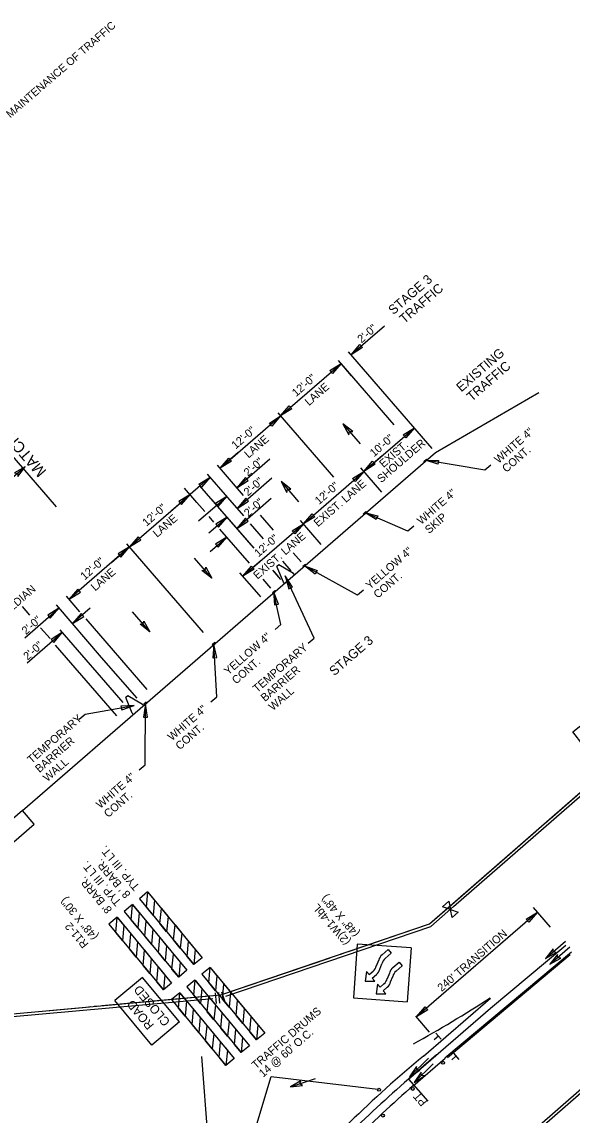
# Model space of a CAD drawing. Extents: x 259983 to 267998, y 211467 to 219827.
# Drawn here: x 265064 to 265890, y 214746 to 216385 of the extents above; entities that cross this region are included whole.
import ezdxf

# ---------------------------------------------------------------- set-up
doc = ezdxf.new("R2010")
doc.units = 0
for name, color, linetype in [('1', 7, 'Continuous'), ('Default', 7, 'Continuous'), ('Level 1', 7, 'Continuous'), ('Level 24', 7, 'Continuous'), ('Level 43', 7, 'Continuous'), ('Level 58', 7, 'Continuous'), ('R-W - CofA', 7, 'Continuous'), ('R_MOT', 7, 'Continuous'), ('R_MOT STAGE 1', 7, 'Continuous'), ('R_MOT STAGE 2', 7, 'Continuous'), ('ROAD', 7, 'Continuous'), ('STATIONING1', 7, 'Continuous')]:
    doc.layers.add(name, color=color, linetype=linetype)

msp = doc.modelspace()

# ---------------------------------------------------------------- linework, layer by layer
at = {"layer": '1'}
for p, q in [((265608.3, 215928.7), (265558.6, 215885.7)), ((265680, 215745.4), (265554.6, 215890.2)), ((265452.7, 215794), (265543.4, 215872.6)), ((265559.2, 215854.3), (265539.5, 215877.1)), ((265623.1, 215780.6), (265543.4, 215872.6)), ((265532.3, 215702.1), (265448.8, 215798.6)), ((265362, 215715.5), (265452.7, 215794)), ((265577.7, 215710.8), (265653.3, 215776.3)), ((265389.2, 215739.1), (265362, 215715.5)), ((265604.9, 215734.4), (265577.7, 215710.8)), ((265397.2, 215674.8), (265358.1, 215720)), ((265436.7, 215729.3), (265387.2, 215686.4)), ((265604.4, 215679.9), (265573.2, 215716)), ((265759.2, 215712.6), (265669.8, 215727.7)), ((265768, 215720.2), (265759.2, 215712.6)), ((265346.9, 215702.4), (265302.2, 215663.8)), ((265373.5, 215671.7), (265342.9, 215706.9)), ((265439.6, 215700.6), (265387.5, 215655.5)), ((265486.9, 215632.3), (265577.7, 215710.8)), ((265327.1, 215664.1), (265308.4, 215685.7)), ((265411.9, 215596.8), (265331.7, 215689.3)), ((265226, 215597.7), (265316.7, 215676.3)), ((265289.5, 215652.7), (265316.7, 215676.3)), ((265329.7, 215636.7), (265372, 215673.3)), ((265353.9, 215663.7), (265349.6, 215668.7)), ((265397.3, 215644.1), (265373.5, 215671.7)), ((265438.7, 215670.1), (265387.1, 215625.4)), ((265338.8, 215650.6), (265327.1, 215664.1)), ((265382.8, 215630.3), (265361, 215655.5)), ((265345.2, 215618.8), (265372.4, 215642.4)), ((265352.4, 215634.9), (265345.3, 215643.1)), ((265442.1, 215623), (265422.7, 215645.4)), ((265513.7, 215601.4), (265482.5, 215637.4)), ((265643.6, 215621.1), (265579.1, 215649.1)), ((265405.8, 215573.2), (265361.7, 215624.2)), ((265412.9, 215595.6), (265382.8, 215630.3)), ((265396.2, 215553.7), (265486.9, 215632.3)), ((265427, 215609.9), (265407.6, 215632.3)), ((265652.4, 215628.8), (265643.6, 215621.1)), ((265336.9, 215469.6), (265222, 215602.3)), ((265347.1, 215590.8), (265372, 215612.3)), ((265226, 215597.8), (265135.3, 215519.2)), ((265198.8, 215574.2), (265226, 215597.8)), ((265483.4, 215575.2), (265471.7, 215588.8)), ((265423.4, 215577.3), (265396.2, 215553.7)), ((265468.3, 215562.1), (265456.2, 215576.1)), ((265567.9, 215525.3), (265488.7, 215569.2)), ((265420.3, 215526), (265391.7, 215558.9)), ((265453.2, 215549), (265441.1, 215563)), ((265448.9, 215554), (265442.9, 215561)), ((265503, 215461), (265459.7, 215554.3)), ((265438.1, 215536), (265426.3, 215549.6)), ((265151.6, 215500.3), (265131.3, 215523.7)), ((265422.9, 215522.9), (265420.3, 215526)), ((265453.2, 215481.6), (265442.2, 215530.7)), ((265576.8, 215533), (265567.9, 215525.3)), ((265076.2, 215495.5), (265065.2, 215508.2)), ((265068.7, 215461.6), (265120.1, 215506.1)), ((265184.1, 215432.2), (265116.2, 215510.7)), ((265167, 215506), (265140.3, 215482.8)), ((265252.4, 215383.9), (265160.8, 215489.7)), ((265072.5, 215424.1), (265125.2, 215469.7)), ((265106.7, 215460.3), (265092.6, 215476.6)), ((265216.4, 215364.4), (265122, 215473.4)), ((265444.4, 215473.9), (265453.2, 215481.6)), ((265494.1, 215453.3), (265503, 215461)), ((265206.9, 215344.5), (265115.1, 215450.6)), ((265357, 215373.1), (265352.7, 215451.4)), ((265237.3, 215370.8), (265184.1, 215432.2)), ((265348.2, 215365.4), (265357, 215373.1)), ((265159.2, 215347.2), (265233.1, 215360)), ((265249.3, 215271.1), (265249.9, 215362.4)), ((265150.4, 215339.5), (265159.2, 215347.2)), ((265240.4, 215263.4), (265249.3, 215271.1))]:
    msp.add_line(p, q, dxfattribs=at)
for points in [[(265575.5, 215896.4), (265558.6, 215885.7), (265571.6, 215900.9)], [(265526.5, 215861.9), (265543.4, 215872.6), (265530.4, 215857.4)], [(265469.6, 215804.7), (265452.7, 215794), (265465.7, 215809.3)], [(265435.8, 215783.3), (265452.7, 215794), (265439.7, 215778.8)], [(265636.3, 215765.6), (265653.3, 215776.3), (265640.3, 215761)], [(265378.9, 215726.2), (265362, 215715.5), (265375, 215730.7)], [(265594.6, 215721.5), (265577.7, 215710.8), (265590.7, 215726)], [(265688.8, 215721.5), (265669.8, 215727.7), (265689.8, 215727.4)], [(265329.9, 215691.7), (265346.9, 215702.4), (265333.9, 215687.2)], [(265400.2, 215701.6), (265387.2, 215686.4), (265404.1, 215697.1)], [(265560.7, 215700.1), (265577.7, 215710.8), (265564.7, 215695.6)], [(265303.7, 215661.1), (265316.7, 215676.3), (265299.8, 215665.6)], [(265303.7, 215661.1), (265316.7, 215676.3), (265299.8, 215665.6)], [(265359, 215658.1), (265372, 215673.3), (265355.1, 215662.6)], [(265400.5, 215670.7), (265387.5, 215655.5), (265404.4, 215666.2)], [(265359.4, 215627.2), (265372.4, 215642.4), (265355.4, 215631.7)], [(265400.1, 215640.6), (265387.1, 215625.4), (265404, 215636.1)], [(265503.9, 215643), (265486.9, 215632.3), (265499.9, 215647.5)], [(265596.2, 215638.7), (265579.1, 215649.1), (265598.5, 215644.2)], [(265470, 215621.6), (265486.9, 215632.3), (265473.9, 215617.1)], [(265239, 215613), (265226, 215597.8), (265242.9, 215608.4)], [(265359, 215597.1), (265372, 215612.3), (265355, 215601.6)], [(265213, 215582.5), (265226, 215597.8), (265209, 215587.1)], [(265413.1, 215564.4), (265396.2, 215553.7), (265409.2, 215569)], [(265504.5, 215557), (265488.7, 215569.2), (265507.4, 215562.2)], [(265470.7, 215537.5), (265459.7, 215554.3), (265465.2, 215535)], [(265148.3, 215534.4), (265135.3, 215519.2), (265152.2, 215529.9)], [(265449.3, 215511.9), (265442.2, 215530.7), (265443.5, 215510.7)], [(265107.1, 215490.9), (265120.1, 215506.1), (265103.2, 215495.4)], [(265153.3, 215498), (265140.3, 215482.8), (265157.2, 215493.5)], [(265112.2, 215454.5), (265125.2, 215469.7), (265108.2, 215459)], [(265356.8, 215431.8), (265352.7, 215451.4), (265350.8, 215431.5)], [(265214.2, 215353.3), (265233.1, 215360), (265213.1, 215359.2)], [(265252.7, 215342.6), (265249.9, 215362.4), (265246.7, 215342.6)], [(265821, 215039.6), (265838, 215050.3), (265824.9, 215035.1)], [(265673.4, 214903.9), (265656.5, 214893.2), (265669.5, 214908.4)]]:
    msp.add_lwpolyline(points, close=True, dxfattribs=at)
at = {"layer": 'Default'}
for p, q in [((265685.2, 215739.3), (265840.1, 215829.1)), ((265065.3, 215202.6), (265685.2, 215739.3)), ((265449.9, 215570.9), (265447.2, 215568.5)), ((265456.8, 215544.9), (265447.2, 215568.5)), ((265471.9, 215558), (265449.9, 215570.9)), ((265473.6, 215556.1), (265471.9, 215558)), ((265458.4, 215543), (265456.8, 215544.9)), ((265223.2, 215374.6), (265220.4, 215372.2)), ((265230.1, 215348.6), (265220.4, 215372.2)), ((265245.2, 215361.7), (265223.2, 215374.6)), ((265246.8, 215359.8), (265245.2, 215361.7)), ((265231.7, 215346.7), (265230.1, 215348.6))]:
    msp.add_line(p, q, dxfattribs=at)
for points in [[(265667.6, 215725.8), (265671.4, 215729.1), (265672.3, 215728.1), (265668.4, 215724.8)], [(265576.9, 215647.2), (265580.7, 215650.6), (265581.6, 215649.6), (265577.7, 215646.3)], [(265486, 215568.6), (265489.9, 215571.9), (265490.7, 215570.9), (265486.9, 215567.6)], [(265444.2, 215532.3), (265440.3, 215529), (265441.2, 215528), (265445, 215531.4)], [(265353.9, 215454.2), (265350, 215450.8), (265350.9, 215449.8), (265354.7, 215453.2)], [(265251.1, 215365.2), (265247.2, 215361.9), (265248.1, 215360.9), (265251.9, 215364.2)]]:
    msp.add_lwpolyline(points, close=True, dxfattribs=at)
at = {"layer": 'Level 43'}
for points in [[(265546.2, 215782), (265572.2, 215752)], [(265069.6, 215717.7), (265039.6, 215691.7)], [(265453.3, 215695.6), (265479.3, 215665.5)], [(265349.3, 215551), (265323.3, 215581)], [(265256.5, 215470.6), (265230.5, 215500.6)], [(265850.2, 214980.9), (265880.3, 215006.9)], [(265856.8, 214972.2), (265886.8, 214998.2)], [(265646.1, 214803.5), (265674.5, 214831.3)], [(265653.2, 214795.2), (265681.6, 214823)], [(265467.3, 214788.4), (265504.9, 214801.1)]]:
    msp.add_lwpolyline(points, dxfattribs=at)
at = {"layer": 'Level 58'}
for points in [[(265560.8, 215770.8), (265546.2, 215782), (265555.2, 215765.9), (265556, 215770.6)], [(265058.4, 215703.1), (265069.6, 215717.7), (265053.5, 215708.7), (265058.2, 215707.9)], [(265467.9, 215684.4), (265453.3, 215695.6), (265462.2, 215679.5), (265463.1, 215684.2)], [(265340.4, 215567.1), (265349.3, 215551), (265334.7, 215562.2), (265339.5, 215562.4)], [(265247.5, 215486.6), (265256.5, 215470.6), (265241.8, 215481.7), (265246.6, 215481.9)], [(265861.4, 214995.5), (265850.2, 214980.9), (265866.3, 214989.8), (265861.6, 214990.7)], [(265868, 214986.8), (265856.8, 214972.2), (265872.9, 214981.1), (265868.2, 214982)], [(265656.4, 214818.8), (265646.1, 214803.5), (265661.6, 214813.4), (265656.8, 214814)], [(265483.2, 214797.7), (265467.3, 214788.4), (265485.6, 214790.6), (265481.5, 214793.2)], [(265663.4, 214810.5), (265653.2, 214795.2), (265668.7, 214805.1), (265663.9, 214805.7)]]:
    msp.add_lwpolyline(points, close=True, dxfattribs=at)
at = {"layer": 'R-W - CofA'}
for p, q in [((265695.8, 215058.5), (265705.2, 215066.7)), ((265705.2, 215066.7), (265707.6, 215054.5)), ((265707.6, 215054.5), (265695.8, 215058.5)), ((265710, 215042.3), (265707.6, 215054.5)), ((265707.6, 215054.5), (265719.3, 215050.5)), ((265719.3, 215050.5), (265710, 215042.3)), ((265354.4, 214929.3), (265355.9, 214913.6)), ((265359.7, 214929.8), (265361.1, 214914)), ((265364, 214930.7), (265369.1, 214915.7)), ((265050.7, 214898.1), (265362.9, 214926.4))]:
    msp.add_line(p, q, dxfattribs=at)
for points in [[(265362.9, 214926.4), (265676, 215032.6), (265937.7, 215260.6), (265891.1, 215320.8), (266161.5, 215534.1)], [(265712.3, 215058.6), (265943.4, 215260), (265916.6, 215294.8)], [(265857, 215190.3), (265937.7, 215260.6), (265913.1, 215292.3)], [(265622.7, 214398.8), (265711.4, 214612.4), (266239.1, 215072.3), (266415.9, 215240.2)], [(265839.2, 215174.8), (265844, 215179)], [(265848.1, 215182.5), (265852.9, 215186.7)], [(265709.5, 215061.8), (265835.1, 215171.2)], [(265554.4, 214991.3), (265676, 215032.6), (265709.5, 215061.8)], [(265370.5, 214924.5), (265678.1, 215028.8), (265712.3, 215058.6)], [(265369.2, 214928.5), (265527, 214982)], [(265532, 214983.8), (265538.1, 214985.8)], [(265543.2, 214987.5), (265549.3, 214989.6)], [(265837.2, 214727.6), (266105.3, 214961.2)], [(265045.3, 214893.4), (265351, 214921.1)], [(265184.6, 214910.2), (265350.6, 214925.3)], [(265050.7, 214898.1), (265155.8, 214907.6)], [(265161.1, 214908.1), (265167.5, 214908.7)], [(265172.9, 214909.2), (265179.3, 214909.8)], [(265840, 214724.5), (265963.3, 214831.9)]]:
    msp.add_lwpolyline(points, dxfattribs=at)
at = {"layer": 'R_MOT'}
for p, q in [((265253.1, 215080.6), (265240.7, 215070.3)), ((265253.1, 215080.6), (265334.9, 214982)), ((265230.2, 215061.6), (265217.9, 215051.4)), ((265230.2, 215061.6), (265312, 214963.1)), ((265240.7, 215070.3), (265322.5, 214971.8)), ((265217.9, 215051.4), (265299.7, 214952.8)), ((265207.3, 215042.6), (265194.9, 215032.3)), ((265194.9, 215032.3), (265276.7, 214933.8)), ((265207.3, 215042.6), (265289.1, 214944.1)), ((265567.7, 215002.4), (265561.9, 214921.7)), ((265648.5, 214996.7), (265567.7, 215002.4)), ((265604.8, 214986.3), (265613.9, 214994.2)), ((265613.9, 214994.2), (265618.6, 214988.8)), ((265648.5, 214996.7), (265642.7, 214915.9)), ((265334.9, 214982), (265322.5, 214971.8)), ((265596.5, 214969.6), (265599.9, 214978.3)), ((265609.5, 214980.9), (265618.6, 214988.8)), ((265312, 214963.1), (265299.7, 214952.8)), ((265312, 214963.1), (265299.7, 214952.8)), ((265347, 214967.4), (265334.7, 214957.2)), ((265347, 214967.4), (265428.8, 214868.9)), ((265581.7, 214961.3), (265579.5, 214946.9)), ((265581.7, 214961.3), (265585.6, 214956.8)), ((265585.6, 214956.8), (265591.3, 214961.8)), ((265601.3, 214964.7), (265604.6, 214972.9)), ((265621.2, 214967.4), (265630.3, 214975.3)), ((265625.8, 214962), (265634.9, 214969.9)), ((265630.3, 214975.3), (265634.9, 214969.9)), ((265245.5, 214952.5), (265203.7, 214917.8)), ((265301, 214885.7), (265245.5, 214952.5)), ((265324.1, 214948.4), (265311.8, 214938.2)), ((265324.1, 214948.4), (265405.9, 214849.9)), ((265334.7, 214957.2), (265416.5, 214858.7)), ((265579.5, 214946.9), (265594.1, 214947)), ((265590.2, 214951.5), (265596.4, 214956.8)), ((265590.2, 214951.5), (265594.1, 214947)), ((265612.8, 214950.8), (265616.3, 214959.4)), ((265617.7, 214945.9), (265620.9, 214954)), ((265289.1, 214944.1), (265276.7, 214933.8)), ((265301.2, 214929.4), (265288.9, 214919.2)), ((265289, 214944.1), (265289, 214944)), ((265301.2, 214929.4), (265383.1, 214830.9)), ((265311.8, 214938.2), (265393.6, 214839.7)), ((265598, 214942.5), (265595.8, 214928)), ((265598, 214942.5), (265601.9, 214938)), ((265601.9, 214938), (265607.6, 214943)), ((265606.6, 214932.6), (265612.7, 214937.9)), ((265606.6, 214932.6), (265610.4, 214928.1)), ((265259.2, 214851), (265203.7, 214917.8)), ((265288.9, 214919.2), (265370.7, 214820.6)), ((265561.9, 214921.7), (265642.7, 214915.8)), ((265595.8, 214928), (265610.4, 214928.1)), ((265301, 214885.7), (265259.2, 214851)), ((265428.8, 214868.9), (265416.5, 214858.7)), ((265689.7, 214864.5), (265683.3, 214858.9)), ((265685.7, 214869.1), (265693.7, 214859.9)), ((265405.9, 214849.9), (265393.6, 214839.7)), ((265405.9, 214849.9), (265393.6, 214839.7)), ((265383.1, 214830.9), (265370.7, 214820.6)), ((265383, 214831), (265382.9, 214830.8)), ((265715.8, 214834.3), (265709.4, 214828.8)), ((265711.9, 214838.9), (265719.9, 214829.7))]:
    msp.add_line(p, q, dxfattribs=at)
for points in [[(265261.2, 215045.7), (265251.2, 215057.8), (265253.3, 215080.3), (265263.3, 215068.2)], [(265238.3, 215026.7), (265228.3, 215038.8), (265230.4, 215061.3), (265240.4, 215049.3)], [(265281.6, 215021), (265271.6, 215033.2), (265273.7, 215055.7), (265283.7, 215043.6)], [(265215.4, 215007.6), (265205.4, 215019.8), (265207.5, 215042.3), (265217.5, 215030.2)], [(265258.8, 215002.1), (265248.8, 215014.2), (265250.9, 215036.7), (265260.9, 215024.6)], [(265302.1, 214996.4), (265292.1, 215008.6), (265294.2, 215031.1), (265304.2, 215019)], [(265235.9, 214983), (265225.8, 214995.2), (265227.9, 215017.7), (265237.9, 215005.6)], [(265279.2, 214977.4), (265269.2, 214989.6), (265271.3, 215012.1), (265281.3, 215000)], [(265322.5, 214971.8), (265312.5, 214983.9), (265314.6, 215006.5), (265324.6, 214994.4)], [(265256.3, 214958.4), (265246.3, 214970.5), (265248.4, 214993.1), (265258.4, 214981)], [(265299.7, 214952.8), (265289.6, 214965), (265291.7, 214987.5), (265301.8, 214975.4)], [(265276.7, 214933.8), (265266.7, 214945.9), (265268.8, 214968.4), (265278.8, 214956.4)], [(265355.1, 214932.5), (265345.1, 214944.7), (265347.2, 214967.2), (265357.2, 214955.1)], [(265332.3, 214913.5), (265322.3, 214925.7), (265324.4, 214948.2), (265334.4, 214936.1)], [(265309.4, 214894.5), (265299.3, 214906.6), (265301.4, 214929.1), (265311.4, 214917.1)], [(265375.6, 214907.9), (265365.6, 214920), (265367.7, 214942.6), (265377.7, 214930.5)], [(265352.7, 214888.9), (265342.7, 214901.1), (265344.8, 214923.6), (265354.8, 214911.5)], [(265396, 214883.3), (265386, 214895.4), (265388.1, 214917.9), (265398.1, 214905.9)], [(265329.8, 214869.9), (265319.8, 214882), (265321.9, 214904.5), (265331.9, 214892.5)], [(265373.2, 214864.3), (265363.2, 214876.4), (265365.2, 214899), (265375.3, 214886.9)], [(265350.2, 214845.3), (265340.2, 214857.4), (265342.3, 214879.9), (265352.3, 214867.8)], [(265416.5, 214858.7), (265406.5, 214870.8), (265408.5, 214893.3), (265418.6, 214881.2)], [(265393.6, 214839.7), (265383.6, 214851.8), (265385.7, 214874.3), (265395.7, 214862.3)], [(265370.7, 214820.6), (265360.7, 214832.8), (265362.7, 214855.3), (265372.8, 214843.2)]]:
    msp.add_lwpolyline(points, close=True, dxfattribs=at)
for centre, major_axis in [((265616.2, 214972.6), (-11.6, 13.4)), ((265620.9, 214967.2), (-11.6, 13.4)), ((265580, 214975.5), (11.6, -13.4)), ((265585.1, 214970.4), (11.6, -13.4)), ((265632.5, 214953.8), (-11.6, 13.4)), ((265637.2, 214948.3), (-11.6, 13.4)), ((265596.3, 214956.6), (11.6, -13.4)), ((265601.4, 214951.6), (11.6, -13.4))]:
    msp.add_ellipse(centre, major_axis=major_axis, ratio=0.9, start_param=6.26006, end_param=6.849246, dxfattribs=at)
at = {"layer": 'R_MOT STAGE 1'}
for p, q in [((265116.5, 215657.7), (264949.5, 215850.6)), ((265767.6, 214906.4), (265880.4, 215001)), ((265699.1, 214831.8), (265889.1, 214991)), ((265887.3, 214986.1), (265703.1, 214832.2)), ((265666.9, 214834.6), (265767.4, 214921.5)), ((265644.7, 214800), (265767.6, 214906.4)), ((265334, 214834.2), (265354.4, 214563.8)), ((265686.8, 214836.5), (265644.7, 214800)), ((265651.1, 214789.7), (265699.4, 214831.5)), ((265644.7, 214800), (265673.5, 214766.8))]:
    msp.add_line(p, q, dxfattribs=at)
for centre in [(265696.4, 214824.6), (265600.5, 214784.1), (265651, 214785.4), (265606.1, 214745.5)]:
    msp.add_circle(centre, 2.25, dxfattribs=at)
for radius, start in [(1921.9, 129.7094), (1909.9, 130.8833), (1897.9, 130.8833)]:
    msp.add_arc((266894.8, 213356.1), radius, start, 138.5667, dxfattribs=at)
at = {"layer": 'R_MOT STAGE 2'}
for p, q in [((265838, 215050.3), (265656.5, 214893.2)), ((265857.6, 215027.6), (265832, 215057.2)), ((265676.1, 214870.5), (265655.3, 214894.6))]:
    msp.add_line(p, q, dxfattribs=at)
msp.add_lwpolyline([(264732.4, 214914.4), (264750.2, 214893.8), (265083.1, 215182), (265065.3, 215202.6)], close=True, dxfattribs=at)
msp.add_lwpolyline([(265353.8, 214522.7), (265438.3, 214804.1), (265598.5, 214785)], dxfattribs=at)
at = {"layer": 'ROAD'}
msp.add_arc((264725.7, 216531.8), 1917.4, 298.8832, 302.8967, dxfattribs=at)

# ---------------------------------------------------------------- texts
at = {"layer": '1'}
for s, height, rotation, p in [('STAGE 3', 14, 40.8733, (265621.7, 215944.9)), ('TRAFFIC', 14, 40.8733, (265638.4, 215931.6)), ('2\'-0"', 12, 40.8833, (265574.1, 215902.6)), ('EXISTING', 14, 40.8733, (265723.7, 215829.2)), ('TRAFFIC', 14, 40.8733, (265739.4, 215815)), ('12\'-0"', 12, 40.8833, (265476, 215822.2)), ('LANE', 12, 40.8833, (265495.2, 215808.5)), ('12\'-0"', 12, 40.8833, (265385.3, 215743.6)), ('LANE', 12, 40.8833, (265404.5, 215730)), ('10\'-0"', 12, 40.8833, (265592.8, 215731.9)), ('WHITE 4"', 12, 40.8833, (265779.7, 215722.1)), ('SHOULDER', 12, 40.8833, (265603.8, 215693.1)), ('EXIST.', 12, 40.8833, (265607, 215715.8)), ('2\'-0"', 12, 40.8933, (265403.7, 215702.7)), ('CONT.', 12, 40.8833, (265791.4, 215708.5)), ('2\'-0"', 12, 40.8933, (265403.6, 215673.2)), ('EXIST. LANE', 12, 40.8833, (265508.7, 215627.1)), ('12\'-0"', 12, 40.8833, (265510.3, 215660.4)), ('WHITE 4"', 12, 40.8833, (265663.7, 215630.4)), ('2\'-0"', 12, 40.8933, (265404, 215642)), ('12\'-0"', 12, 40.8833, (265251.5, 215627.8)), ('LANE', 12, 40.8833, (265267.3, 215611.2)), ('SKIP', 12, 40.8833, (265675.5, 215616.8)), ('EXIST. LANE', 12, 40.8833, (265417.9, 215548.5)), ('12\'-0"', 12, 40.8833, (265419.5, 215581.9)), ('YELLOW 4"', 12, 40.8833, (265586.6, 215533.4)), ('12\'-0"', 12, 40.8833, (265158.6, 215547.3)), ('LANE', 12, 40.8833, (265174.4, 215530.8)), ('CONT.', 12, 40.8833, (265598.4, 215519.8)), ('MEDIAN', 12, 40.8933, (265039.3, 215492)), ('2\'-0"', 12, 40.8933, (265070.6, 215465.5)), ('YELLOW 4"', 12, 40.8833, (265374.1, 215404.9)), ('2\'-0"', 12, 40.8933, (265073, 215427.3)), ('TEMPORARY', 12, 40.8833, (265417.4, 215378.7)), ('STAGE 3', 14, 40.8933, (265533.1, 215403.7)), ('CONT.', 12, 40.8833, (265385.9, 215391.3)), ('BARRIER', 12, 40.8833, (265429.2, 215365.1)), ('WALL', 12, 40.8833, (265441, 215351.5)), ('WHITE 4"', 12, 40.8833, (265289.5, 215306.4)), ('TEMPORARY', 12, 40.8833, (265079, 215272.2)), ('CONT.', 12, 40.8833, (265301.3, 215292.8)), ('BARRIER', 12, 40.8833, (265090.8, 215258.6)), ('WALL', 12, 40.8833, (265102.6, 215245)), ('WHITE 4"', 12, 40.8833, (265182.1, 215204.8)), ('CONT.', 12, 40.8833, (265193.9, 215191.2)), ("240' TRANSITION", 12, 40.8733, (265694.3, 214930.5))]:
    msp.add_text(s, height=height, rotation=rotation, dxfattribs=at).set_placement(p)
at = {"layer": 'Level 1'}
msp.add_text('MAINTENANCE OF TRAFFIC', height=11.7, rotation=40.8733, dxfattribs=at).set_placement((265047.1, 216239.9))
at = {"layer": 'Level 24'}
for s, p in [('TRAFFIC DRUMS', (265415.7, 214814.4)), ("14 @ 60' O.C.", (265426.4, 214802.1))]:
    msp.add_text(s, height=12, rotation=40.8835, dxfattribs=at).set_placement(p)
at = {"layer": 'R_MOT'}
for s, height, rotation, p in [('TYP. III LT.', 12, 129.7024, (265242.1, 215088.8)), ('TYP. III LT.', 12, 129.7024, (265214.4, 215065.8)), ("8 ' BARR.", 12, 129.7024, (265228.3, 215077.3)), ("8' BARR.", 12, 129.7024, (265200.6, 215054.3)), ('(48" X 48")', 12, 130.8833, (265571.8, 215019.3)), ('(48" X 30")', 12, 129.7024, (265179.6, 215014.5)), ('(2)W1-4bL', 12, 130.8833, (265558.2, 215006.9)), ('R11-2', 12, 129.7024, (265165.1, 215002.5)), ('CLOSED', 13.22, 129.7024, (265287.8, 214886.2)), ('ROAD', 13.15, 129.7024, (265263.4, 214881.1))]:
    msp.add_text(s, height=height, rotation=rotation, dxfattribs=at).set_placement(p)
at = {"layer": 'R_MOT STAGE 1'}
msp.add_text('PT', height=12, rotation=130.8833, dxfattribs=at).set_placement((265673.1, 214765.9))
at = {"layer": 'STATIONING1'}
msp.add_text('MATCH LINE', height=16.5, rotation=130.8833, dxfattribs=at).set_placement((265102.1, 215711.3))

doc.saveas('drawing.dxf')
